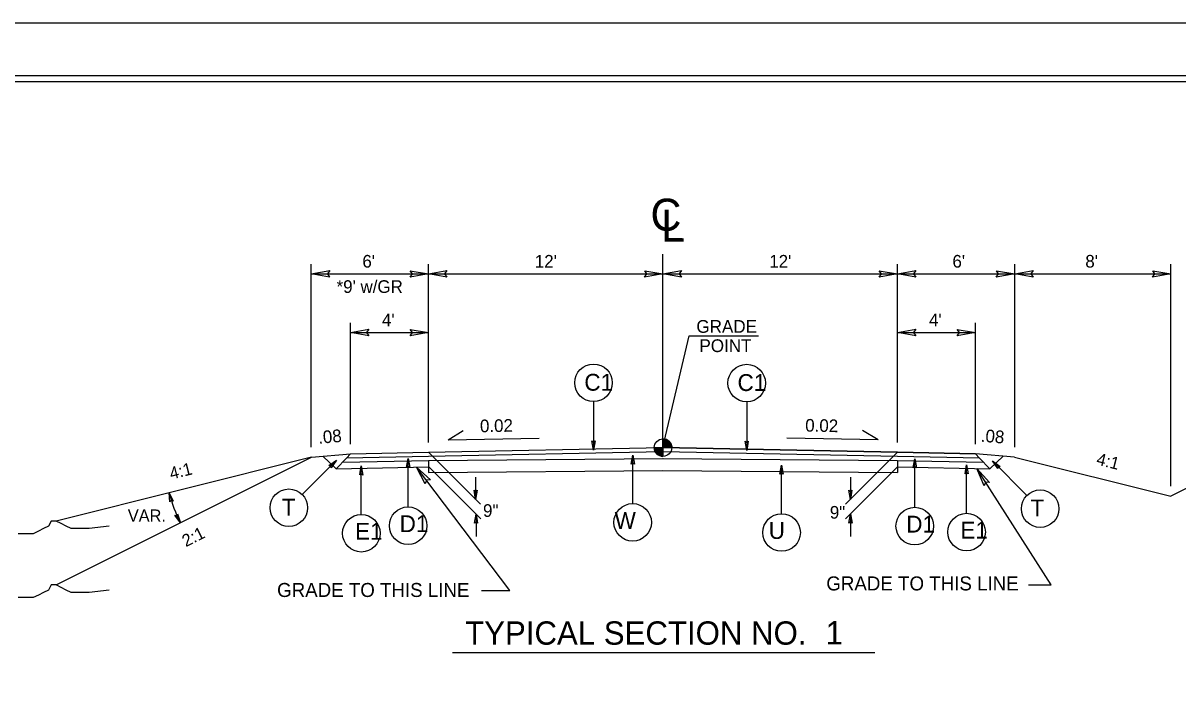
# Model space of a CAD drawing. Extents: x 573771 to 574316, y -53454 to -53190.
# Drawn here: x 574083 to 574201.2, y -53257.3 to -53189.5 of the extents above; entities that cross this region are included whole.
import ezdxf

# ---------------------------------------------------------------- set-up
doc = ezdxf.new("R2010")
doc.units = 0
for name, color, linetype in [('Sheet Cutting Line CELL', 7, 'Continuous'), ('Sheet Plot Border Inside CELL', 7, 'Continuous'), ('Sheet Plot Border Outside CELL', 7, 'Continuous'), ('Sheet Typical CELL', 7, 'Continuous'), ('Typical Grade Point Symbol CELL', 7, 'Continuous'), ('Typical ID Circle CELL', 7, 'Continuous'), ('Typical Pavement Slope CELL', 7, 'Continuous'), ('Typical Pavement Slope Information CELL', 7, 'Continuous'), ('Typical Shoulder Slope CELL', 7, 'Continuous'), ('Typical Shoulder Slope Information CELL', 7, 'Continuous'), ('Typical Slope Point Local CELL', 7, 'Continuous'), ('Typical Terminator CELL', 7, 'Continuous'), ('Typical Text Centerline CELL', 7, 'Continuous'), ('Typical Text General CELL', 7, 'Continuous'), ('Typical Text Grade Point CELL', 7, 'Continuous'), ('Typical Text ID Circle CELL', 7, 'Continuous'), ('Typical Text Label CELL', 7, 'Continuous')]:
    doc.layers.add(name, color=color, linetype=linetype)

msp = doc.modelspace()

# ---------------------------------------------------------------- linework, layer by layer
at = {"layer": 'Sheet Cutting Line CELL'}
msp.add_line((574316.11, -53189.54), (573911.95, -53189.54), dxfattribs=at)
at = {"layer": 'Sheet Plot Border Inside CELL'}
msp.add_lwpolyline([(574315.03, -53194.93), (573915.07, -53194.93), (573915.07, -53448.15), (574315.03, -53448.15)], close=True, dxfattribs=at)
at = {"layer": 'Sheet Plot Border Outside CELL'}
msp.add_lwpolyline([(574316.11, -53189.54), (573911.95, -53189.54), (573911.95, -53453.54), (574316.11, -53453.54)], close=True, dxfattribs=at)
at = {"layer": 'Sheet Typical CELL'}
msp.add_lwpolyline([(574312.03, -53195.54), (573952.03, -53195.54), (573952.03, -53447.54), (574312.03, -53447.54)], close=True, dxfattribs=at)
at = {"layer": 'Typical Grade Point Symbol CELL'}
for p, q in [((574148.51, -53232.96), (574148.51, -53232.06)), ((574147.62, -53232.96), (574148.51, -53232.96)), ((574149.41, -53232.96), (574148.51, -53232.96)), ((574148.51, -53233.86), (574148.51, -53232.96)), ((574148.51, -53232.96), (574148.51, -53233.86))]:
    msp.add_line(p, q, dxfattribs=at)
for points in [[(574148.52, -53232.06), (574148.52, -53232.06), (574148.52, -53232.96)], [(574148.54, -53232.06), (574148.54, -53232.96)], [(574148.56, -53232.07), (574148.56, -53232.96)], [(574148.57, -53232.07), (574148.57, -53232.96)], [(574148.59, -53232.07), (574148.59, -53232.96)], [(574148.61, -53232.07), (574148.61, -53232.96)], [(574148.63, -53232.07), (574148.63, -53232.96)], [(574148.64, -53232.07), (574148.64, -53232.96)], [(574148.66, -53232.08), (574148.66, -53232.96)], [(574148.68, -53232.08), (574148.68, -53232.96)], [(574148.7, -53232.08), (574148.7, -53232.96)], [(574148.72, -53232.09), (574148.72, -53232.96)], [(574148.73, -53232.09), (574148.73, -53232.96)], [(574148.75, -53232.1), (574148.75, -53232.96)], [(574148.77, -53232.1), (574148.77, -53232.96)], [(574148.79, -53232.11), (574148.79, -53232.96)], [(574148.81, -53232.11), (574148.81, -53232.96)], [(574148.82, -53232.12), (574148.82, -53232.96)], [(574148.84, -53232.13), (574148.84, -53232.96)], [(574148.86, -53232.14), (574148.86, -53232.96)], [(574148.88, -53232.14), (574148.88, -53232.96)], [(574148.9, -53232.15), (574148.9, -53232.96)], [(574148.91, -53232.16), (574148.91, -53232.96)], [(574148.93, -53232.17), (574148.93, -53232.96)], [(574148.95, -53232.18), (574148.95, -53232.96)], [(574147.62, -53232.96), (574147.62, -53233.06)], [(574147.64, -53232.96), (574147.64, -53233.16)], [(574147.66, -53232.96), (574147.66, -53233.23)], [(574147.67, -53232.96), (574147.67, -53233.28)], [(574147.69, -53232.96), (574147.69, -53233.32)], [(574147.71, -53232.96), (574147.71, -53233.36)], [(574147.73, -53232.96), (574147.73, -53233.39)], [(574147.75, -53232.96), (574147.75, -53233.43)], [(574147.76, -53232.96), (574147.76, -53233.45)], [(574147.78, -53232.96), (574147.78, -53233.48)], [(574147.8, -53232.96), (574147.8, -53233.5)], [(574147.82, -53232.96), (574147.82, -53233.52)], [(574147.84, -53232.96), (574147.84, -53233.55)], [(574147.85, -53232.96), (574147.85, -53233.57)], [(574147.87, -53232.96), (574147.87, -53233.59)], [(574147.89, -53232.96), (574147.89, -53233.6)], [(574147.91, -53232.96), (574147.91, -53233.62)], [(574147.92, -53232.96), (574147.92, -53233.64)], [(574147.94, -53232.96), (574147.94, -53233.65)], [(574147.96, -53232.96), (574147.96, -53233.67)], [(574147.98, -53232.96), (574147.98, -53233.68)], [(574148, -53232.96), (574148, -53233.69)], [(574148.01, -53232.96), (574148.01, -53233.7)], [(574148.03, -53232.96), (574148.03, -53233.72)], [(574148.05, -53232.96), (574148.05, -53233.73)], [(574148.07, -53232.96), (574148.07, -53233.74)], [(574148.09, -53232.96), (574148.09, -53233.75)], [(574148.1, -53232.96), (574148.1, -53233.76)], [(574148.12, -53232.96), (574148.12, -53233.77)], [(574148.14, -53232.96), (574148.14, -53233.77)], [(574148.16, -53232.96), (574148.16, -53233.78)], [(574148.18, -53232.96), (574148.18, -53233.79)], [(574148.19, -53232.96), (574148.19, -53233.8)], [(574148.21, -53232.96), (574148.21, -53233.8)], [(574148.23, -53232.96), (574148.23, -53233.81)], [(574148.25, -53232.96), (574148.25, -53233.82)], [(574148.26, -53232.96), (574148.26, -53233.82)], [(574148.28, -53232.96), (574148.28, -53233.83)], [(574148.3, -53232.96), (574148.3, -53233.83)], [(574148.32, -53232.96), (574148.32, -53233.83)], [(574148.34, -53232.96), (574148.34, -53233.84)], [(574148.35, -53232.96), (574148.35, -53233.84)], [(574148.37, -53232.96), (574148.37, -53233.84)], [(574148.39, -53232.96), (574148.39, -53233.85)], [(574148.41, -53232.96), (574148.41, -53233.85)], [(574148.43, -53232.96), (574148.43, -53233.85)], [(574148.44, -53232.96), (574148.44, -53233.85)], [(574148.46, -53232.96), (574148.46, -53233.85)], [(574148.48, -53232.96), (574148.48, -53233.86)], [(574148.5, -53232.96), (574148.5, -53233.86), (574148.5, -53233.86)], [(574148.97, -53232.19), (574148.97, -53232.96)], [(574148.98, -53232.2), (574148.98, -53232.96)], [(574149, -53232.21), (574149, -53232.96)], [(574149.02, -53232.22), (574149.02, -53232.96)], [(574149.04, -53232.24), (574149.04, -53232.96)], [(574149.06, -53232.25), (574149.06, -53232.96)], [(574149.07, -53232.26), (574149.07, -53232.96)], [(574149.09, -53232.28), (574149.09, -53232.96)], [(574149.11, -53232.3), (574149.11, -53232.96)], [(574149.13, -53232.31), (574149.13, -53232.96)], [(574149.15, -53232.33), (574149.15, -53232.96)], [(574149.16, -53232.35), (574149.16, -53232.96)], [(574149.18, -53232.37), (574149.18, -53232.96)], [(574149.2, -53232.39), (574149.2, -53232.96)], [(574149.22, -53232.41), (574149.22, -53232.96)], [(574149.24, -53232.43), (574149.24, -53232.96)], [(574149.25, -53232.46), (574149.25, -53232.96)], [(574149.27, -53232.49), (574149.27, -53232.96)], [(574149.29, -53232.52), (574149.29, -53232.96)], [(574149.31, -53232.55), (574149.31, -53232.96)], [(574149.33, -53232.59), (574149.33, -53232.96)], [(574149.34, -53232.63), (574149.34, -53232.96)], [(574149.36, -53232.68), (574149.36, -53232.96)], [(574149.38, -53232.74), (574149.38, -53232.96)], [(574149.4, -53232.83), (574149.4, -53232.96)]]:
    msp.add_lwpolyline(points, dxfattribs=at)
msp.add_circle((574148.51, -53232.96), 0.895, dxfattribs=at)
for start, end in [(359.9905, 89.9905), (179.9905, 269.9905)]:
    msp.add_arc((574148.51, -53232.96), 0.895, start, end, dxfattribs=at)
at = {"layer": 'Typical ID Circle CELL'}
for p, q in [((574141.4, -53228.25), (574141.4, -53233.22)), ((574157.08, -53228.28), (574157.08, -53233.25)), ((574111.57, -53237.75), (574115.08, -53234.24)), ((574122.42, -53239.03), (574122.42, -53234.06)), ((574145.41, -53238.69), (574145.41, -53233.72)), ((574174.28, -53239.07), (574174.28, -53234.1)), ((574185.76, -53237.85), (574182.25, -53234.33)), ((574117.63, -53239.8), (574117.63, -53234.82)), ((574160.65, -53239.72), (574160.65, -53234.75)), ((574179.59, -53239.68), (574179.59, -53234.71))]:
    msp.add_line(p, q, dxfattribs=at)
for centre in [(574141.4, -53226.33), (574157.08, -53226.36), (574110.21, -53239.11), (574187.12, -53239.21), (574122.42, -53240.95), (574145.41, -53240.61), (574174.28, -53240.99), (574117.63, -53241.72), (574160.65, -53241.65), (574179.59, -53241.6)]:
    msp.add_circle(centre, 1.92, dxfattribs=at)
at = {"layer": 'Typical Pavement Slope CELL'}
for p in [(574124.52, -53233.44), (574172.5, -53233.44)]:
    msp.add_line(p, (574148.51, -53232.96), dxfattribs=at)
at = {"layer": 'Typical Pavement Slope Information CELL'}
for p, q in [((574148.51, -53232.96), (574148.51, -53213.19)), ((574112.51, -53232.93), (574112.51, -53214.19)), ((574124.51, -53232.44), (574124.51, -53214.19)), ((574172.51, -53232.44), (574172.51, -53214.19)), ((574184.51, -53232.93), (574184.51, -53214.19)), ((574200.51, -53236.91), (574200.51, -53214.19)), ((574112.51, -53215.19), (574124.51, -53215.19)), ((574124.51, -53215.19), (574148.51, -53215.19)), ((574148.51, -53215.19), (574172.51, -53215.19)), ((574172.51, -53215.19), (574184.51, -53215.19)), ((574184.51, -53215.19), (574200.51, -53215.19)), ((574116.51, -53232.6), (574116.51, -53220.19)), ((574180.51, -53232.6), (574180.51, -53220.19)), ((574116.51, -53221.19), (574124.51, -53221.19)), ((574172.51, -53221.19), (574180.51, -53221.19)), ((574126.51, -53232.17), (574128.07, -53231.22)), ((574126.51, -53232.17), (574135.83, -53231.98)), ((574170.52, -53232.17), (574161.2, -53231.98)), ((574170.52, -53232.17), (574168.95, -53231.22)), ((574124.52, -53233.44), (574148.51, -53232.96)), ((574148.51, -53232.96), (574172.5, -53233.44)), ((574113.7, -53233.84), (574115.05, -53235.13)), ((574115.05, -53235.13), (574116.11, -53234.03)), ((574115.71, -53234.45), (574124.54, -53234.27)), ((574116.11, -53234.03), (574116.52, -53233.6)), ((574124.52, -53233.86), (574116.11, -53234.03)), ((574116.52, -53233.6), (574124.52, -53233.44)), ((574129.83, -53238.76), (574124.51, -53233.44)), ((574148.51, -53233.38), (574124.52, -53233.86)), ((574124.52, -53234.27), (574148.52, -53234.06)), ((574124.52, -53234.27), (574124.52, -53235.52)), ((574172.5, -53233.86), (574148.51, -53233.38)), ((574148.51, -53234.06), (574172.5, -53234.27)), ((574167.19, -53238.76), (574172.51, -53233.44)), ((574172.5, -53233.44), (574180.5, -53233.6)), ((574180.91, -53234.03), (574172.5, -53233.86)), ((574172.5, -53234.27), (574181.32, -53234.45)), ((574172.5, -53234.27), (574172.5, -53235.52)), ((574180.5, -53233.6), (574180.91, -53234.03)), ((574181.97, -53235.13), (574180.91, -53234.03)), ((574183.32, -53233.84), (574181.97, -53235.13)), ((574115.05, -53235.13), (574124.55, -53234.94)), ((574124.52, -53235.52), (574148.51, -53235.31)), ((574129.87, -53240.26), (574124.55, -53234.94)), ((574148.51, -53235.31), (574172.5, -53235.52)), ((574167.18, -53240.26), (574172.5, -53234.94)), ((574172.5, -53234.94), (574181.97, -53235.13)), ((574129.33, -53235.98), (574129.33, -53238.26)), ((574167.69, -53235.98), (574167.69, -53238.26)), ((574129.37, -53239.76), (574129.37, -53242.05)), ((574167.69, -53239.75), (574167.69, -53242.04))]:
    msp.add_line(p, q, dxfattribs=at)
at = {"layer": 'Typical Shoulder Slope CELL'}
for p, q in [((574112.52, -53233.94), (574116.52, -53233.6)), ((574116.52, -53233.6), (574124.52, -53233.44)), ((574180.5, -53233.6), (574172.5, -53233.44)), ((574184.5, -53233.94), (574180.5, -53233.6))]:
    msp.add_line(p, q, dxfattribs=at)
at = {"layer": 'Typical Slope Point Local CELL'}
for p, q in [((574216.4, -53229.98), (574200.5, -53237.94)), ((574112.52, -53233.94), (574086.39, -53240.47)), ((574086.39, -53247), (574112.52, -53233.94)), ((574184.5, -53233.94), (574200.5, -53237.94))]:
    msp.add_line(p, q, dxfattribs=at)
for points in [[(574091.83, -53240.99), (574089.76, -53241.25), (574089.24, -53241.25), (574088.46, -53241.25), (574087.94, -53241.25), (574087.42, -53240.99), (574086.91, -53240.73), (574086.39, -53240.47), (574085.87, -53240.47), (574085.61, -53240.99), (574085.09, -53241.25), (574084.57, -53241.51), (574084.05, -53241.77), (574083.53, -53241.77), (574083.02, -53241.77), (574082.5, -53241.77)], [(574091.83, -53247.53), (574089.76, -53247.78), (574089.24, -53247.78), (574088.46, -53247.78), (574087.94, -53247.78), (574087.42, -53247.53), (574086.91, -53247.26), (574086.39, -53247), (574085.87, -53247), (574085.61, -53247.53), (574085.09, -53247.78), (574084.57, -53248.04), (574084.05, -53248.3), (574083.53, -53248.3), (574083.02, -53248.3), (574082.5, -53248.3)]]:
    msp.add_lwpolyline(points, dxfattribs=at)
msp.add_arc((574112.52, -53233.94), 15, 194.0362, 206.5659, dxfattribs=at)
at = {"layer": 'Typical Terminator CELL'}
for points in [[(574114.39, -53215.52), (574112.51, -53215.19), (574114.4, -53214.86), (574114.16, -53215.19)], [(574122.64, -53214.87), (574124.51, -53215.19), (574122.63, -53215.53), (574122.87, -53215.19)], [(574126.39, -53215.52), (574124.51, -53215.19), (574126.4, -53214.86), (574126.16, -53215.19)], [(574146.64, -53214.87), (574148.51, -53215.19), (574146.63, -53215.53), (574146.87, -53215.19)], [(574150.39, -53215.52), (574148.51, -53215.19), (574150.4, -53214.86), (574150.16, -53215.19)], [(574170.64, -53214.87), (574172.51, -53215.19), (574170.63, -53215.53), (574170.87, -53215.19)], [(574174.39, -53215.52), (574172.51, -53215.19), (574174.4, -53214.86), (574174.16, -53215.19)], [(574182.64, -53214.87), (574184.51, -53215.19), (574182.63, -53215.53), (574182.87, -53215.19)], [(574186.39, -53215.52), (574184.51, -53215.19), (574186.4, -53214.86), (574186.16, -53215.19)], [(574198.64, -53214.87), (574200.51, -53215.19), (574198.63, -53215.53), (574198.87, -53215.19)], [(574118.39, -53221.52), (574116.51, -53221.19), (574118.4, -53220.86), (574118.16, -53221.19)], [(574122.64, -53220.87), (574124.51, -53221.19), (574122.63, -53221.53), (574122.87, -53221.19)], [(574174.39, -53221.52), (574172.51, -53221.19), (574174.4, -53220.86), (574174.16, -53221.19)], [(574178.64, -53220.87), (574180.51, -53221.19), (574178.63, -53221.53), (574178.87, -53221.19)], [(574141.56, -53232.28), (574141.4, -53233.22), (574141.23, -53232.28), (574141.4, -53232.4)], [(574157.24, -53232.31), (574157.08, -53233.25), (574156.91, -53232.31), (574157.08, -53232.43)], [(574114.31, -53234.79), (574115.08, -53234.24), (574114.54, -53235.02), (574114.5, -53234.82)], [(574122.26, -53235), (574122.42, -53234.06), (574122.59, -53235), (574122.42, -53234.88)], [(574145.25, -53234.65), (574145.41, -53233.72), (574145.58, -53234.66), (574145.41, -53234.54)], [(574174.12, -53235.04), (574174.28, -53234.1), (574174.45, -53235.04), (574174.28, -53234.92)], [(574182.8, -53235.11), (574182.25, -53234.33), (574183.03, -53234.88), (574182.83, -53234.91)], [(574117.47, -53235.76), (574117.63, -53234.82), (574117.8, -53235.77), (574117.63, -53235.65)], [(574124.17, -53236.66), (574123.29, -53234.97), (574124.7, -53236.27), (574124.29, -53236.28)], [(574160.48, -53235.69), (574160.65, -53234.75), (574160.81, -53235.69), (574160.65, -53235.57)], [(574179.43, -53235.65), (574179.59, -53234.71), (574179.76, -53235.65), (574179.59, -53235.53)], [(574181.38, -53236.86), (574180.64, -53235.11), (574181.94, -53236.52), (574181.53, -53236.49)], [(574098.04, -53238.52), (574097.97, -53237.57), (574098.36, -53238.45), (574098.17, -53238.37)], [(574129.5, -53237.33), (574129.33, -53238.26), (574129.17, -53237.32), (574129.33, -53237.44)], [(574167.85, -53237.33), (574167.69, -53238.26), (574167.52, -53237.32), (574167.69, -53237.44)], [(574098.83, -53239.73), (574099.11, -53240.65), (574098.54, -53239.88), (574098.74, -53239.91)], [(574129.21, -53240.7), (574129.37, -53239.76), (574129.54, -53240.7), (574129.37, -53240.58)], [(574167.53, -53240.69), (574167.69, -53239.75), (574167.86, -53240.69), (574167.69, -53240.57)]]:
    msp.add_lwpolyline(points, close=True, dxfattribs=at)
at = {"layer": 'Typical Text Grade Point CELL'}
for p, q in [((574148.51, -53232.96), (574151.2, -53221.53)), ((574151.2, -53221.53), (574158.28, -53221.53)), ((574132.83, -53247.57), (574123.29, -53234.97)), ((574188.24, -53246.99), (574180.64, -53235.11)), ((574185.91, -53246.99), (574188.24, -53246.99)), ((574129.93, -53247.57), (574132.83, -53247.57))]:
    msp.add_line(p, q, dxfattribs=at)
at = {"layer": 'Typical Text Label CELL'}
msp.add_line((574126.98, -53253.92), (574170.19, -53253.92), dxfattribs=at)

# ---------------------------------------------------------------- texts
at = {"layer": 'Typical Pavement Slope Information CELL'}
for s, p in [("6'", (574117.74, -53214.55)), ("12'", (574135.39, -53214.55)), ("12'", (574159.39, -53214.55)), ("6'", (574178.14, -53214.55)), ("8'", (574191.74, -53214.55)), ("*9' w/GR", (574115.1, -53217.14)), ("4'", (574119.74, -53220.55)), ("4'", (574175.74, -53220.55)), ('9"', (574130.09, -53240.05)), ('9"', (574165.59, -53240.23))]:
    msp.add_text(s, height=1.295, dxfattribs=at).set_placement(p)
for s, rotation, p in [('0.02 ', 1.1457, (574129.79, -53231.4)), ('0.02', 358.8543, (574163.06, -53231.32))]:
    msp.add_text(s, height=1.295, rotation=rotation, dxfattribs=at).set_placement(p)
at = {"layer": 'Typical Shoulder Slope Information CELL'}
for rotation, p in [(4.7607, (574113.27, -53232.57)), (355.2393, (574181, -53232.35))]:
    msp.add_text('.08', height=1.295, rotation=rotation, dxfattribs=at).set_placement(p)
at = {"layer": 'Typical Slope Point Local CELL'}
for s, rotation, p in [('4:1', 345.9638, (574192.8, -53234.68)), ('4:1', 14.0362, (574098.17, -53236.24)), ('2:1', 26.5659, (574099.67, -53243.16))]:
    msp.add_text(s, height=1.25, rotation=rotation, dxfattribs=at).set_placement(p)
msp.add_text('VAR.', height=1.25, dxfattribs=at).set_placement((574093.73, -53240.54))
at = {"layer": 'Typical Text Centerline CELL'}
msp.add_text('C', height=3.28, dxfattribs=at).set_placement((574147.23, -53210.78))
msp.add_text('L', height=3.28, rotation=359.9469, dxfattribs=at).set_placement((574148.32, -53211.9))
at = {"layer": 'Typical Text General CELL'}
for p in [(574165.23, -53247.57), (574109.01, -53248.24)]:
    msp.add_text('GRADE TO THIS LINE', height=1.4323, dxfattribs=at).set_placement(p)
at = {"layer": 'Typical Text Grade Point CELL'}
for s, p in [('GRADE', (574151.93, -53221.22)), ('POINT', (574152.24, -53223.19))]:
    msp.add_text(s, height=1.305, dxfattribs=at).set_placement(p)
at = {"layer": 'Typical Text ID Circle CELL'}
for s, p in [('C1', (574140.46, -53227.14)), ('C1', (574156.14, -53227.17)), ('T ', (574109.49, -53239.91)), ('T ', (574186.13, -53240)), ('D1', (574121.55, -53241.61)), ('W ', (574143.56, -53241.27)), ('D1', (574173.41, -53241.65)), ('E1', (574116.99, -53242.38)), ('U ', (574159.33, -53242.3)), ('E1', (574178.95, -53242.26))]:
    msp.add_text(s, height=1.722, dxfattribs=at).set_placement(p)
at = {"layer": 'Typical Text Label CELL'}
for s, height, p in [('TYPICAL SECTION NO.  ', 2.3871, (574128.26, -53253.12)), ('1 ', 2.387, (574165.16, -53253.09))]:
    msp.add_text(s, height=height, dxfattribs=at).set_placement(p)

doc.saveas('drawing.dxf')
